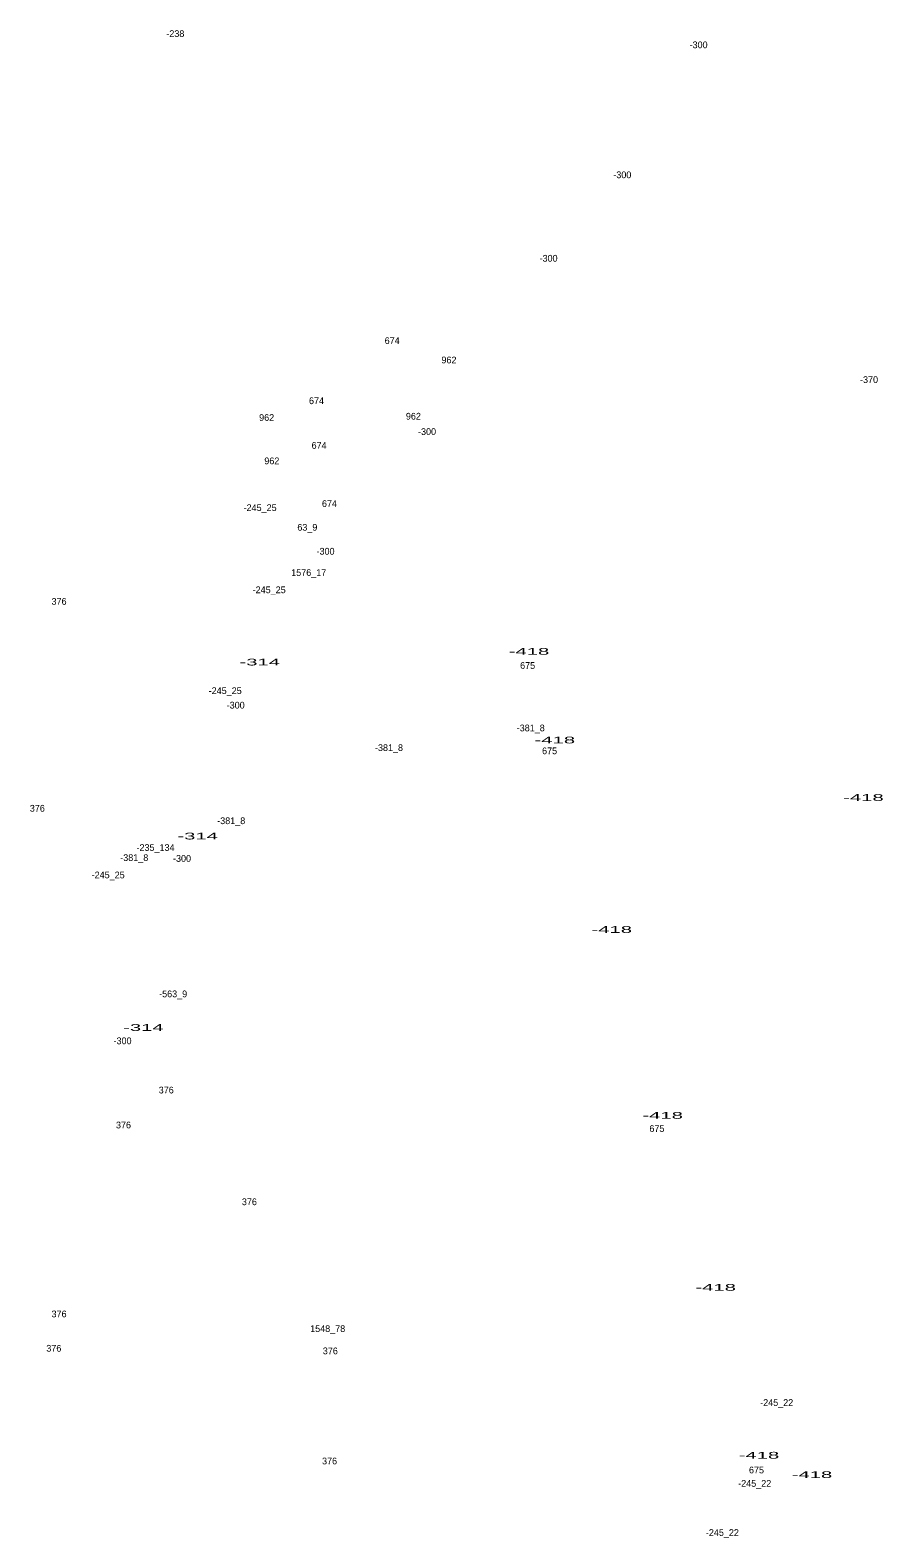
# Model space of a CAD drawing. Extents: x -660434 to -656144, y -997850 to -994016.
# Drawn here: x -660069 to -659563, y -996994 to -996099 of the extents above; entities that cross this region are included whole.
import ezdxf
from ezdxf.enums import TextEntityAlignment as Align

# ---------------------------------------------------------------- set-up
doc = ezdxf.new("R2010")
doc.units = 0
doc.header["$LTSCALE"] = 1.6
doc.layers.add('24', color=7, linetype='Continuous')

msp = doc.modelspace()

# ---------------------------------------------------------------- texts
at = {"layer": '24'}
for s, p in [('-238', (-659982.945, -996102.92)), ('-300', (-659672.143, -996109.59)), ('-300', (-659717.453, -996186.8)), ('-300', (-659761.243, -996236.36)), ('674', (-659854.153, -996285.26)), ('962', (-659820.418, -996296.77)), ('-370', (-659570.904, -996308.44)), ('674', (-659899.083, -996320.99)), ('962', (-659928.708, -996330.96)), ('962', (-659841.538, -996330.19)), ('-300', (-659833.433, -996339.31)), ('674', (-659897.543, -996347.5)), ('962', (-659925.638, -996356.7)), ('-245_25', (-659932.596, -996384.5)), ('674', (-659891.403, -996382.07)), ('63_9', (-659904.536, -996396.16)), ('-300', (-659893.723, -996410.38)), ('1576_17', (-659903.708, -996423.05)), ('376', (-660052.008, -996440.16)), ('-245_25', (-659927.216, -996433.29)), ('675', (-659773.708, -996478.23)), ('-245_25', (-659953.336, -996493.22)), ('-300', (-659947.103, -996501.81)), ('-381_8', (-659771.846, -996515.34)), ('-381_8', (-659856.046, -996527.06)), ('675', (-659760.648, -996528.94)), ('376', (-660064.918, -996563.05)), ('-381_8', (-659949.746, -996570.47)), ('-381_8', (-660007.346, -996592.36)), ('-235_134', (-659994.729, -996586.39)), ('-300', (-659978.973, -996592.85)), ('-245_25', (-660022.836, -996602.65)), ('-563_9', (-659984.243, -996673.3)), ('-300', (-660014.303, -996701.19)), ('376', (-659988.358, -996730.44)), ('376', (-660013.738, -996751.21)), ('675', (-659696.908, -996753.29)), ('376', (-659938.958, -996796.79)), ('376', (-660052.008, -996863.41)), ('1548_78', (-659892.457, -996872.15)), ('376', (-660055.128, -996883.8)), ('376', (-659890.888, -996885.35)), ('-245_22', (-659625.756, -996916.04)), ('376', (-659891.338, -996950.77)), ('675', (-659637.768, -996956.12)), ('-245_22', (-659638.806, -996964.06)), ('-245_22', (-659658.006, -996993.25))]:
    msp.add_text(s, height=4, dxfattribs=at).set_placement(p, align=Align.CENTER)
at = {"layer": '24', "width": 2.25}
for s, p in [('-314', (-659932.806, -996476.22)), ('-418', (-659772.876, -996469.89)), ('-418', (-659757.516, -996522.52)), ('-418', (-659574.226, -996556.67)), ('-314', (-659969.676, -996579.56)), ('-418', (-659723.716, -996635.07)), ('-314', (-660001.926, -996693.27)), ('-418', (-659693.496, -996745.48)), ('-418', (-659662.006, -996847.66)), ('-418', (-659636.286, -996947.35)), ('-418', (-659604.796, -996958.87))]:
    msp.add_text(s, height=4, dxfattribs=at).set_placement(p, align=Align.CENTER)

doc.saveas('drawing.dxf')
